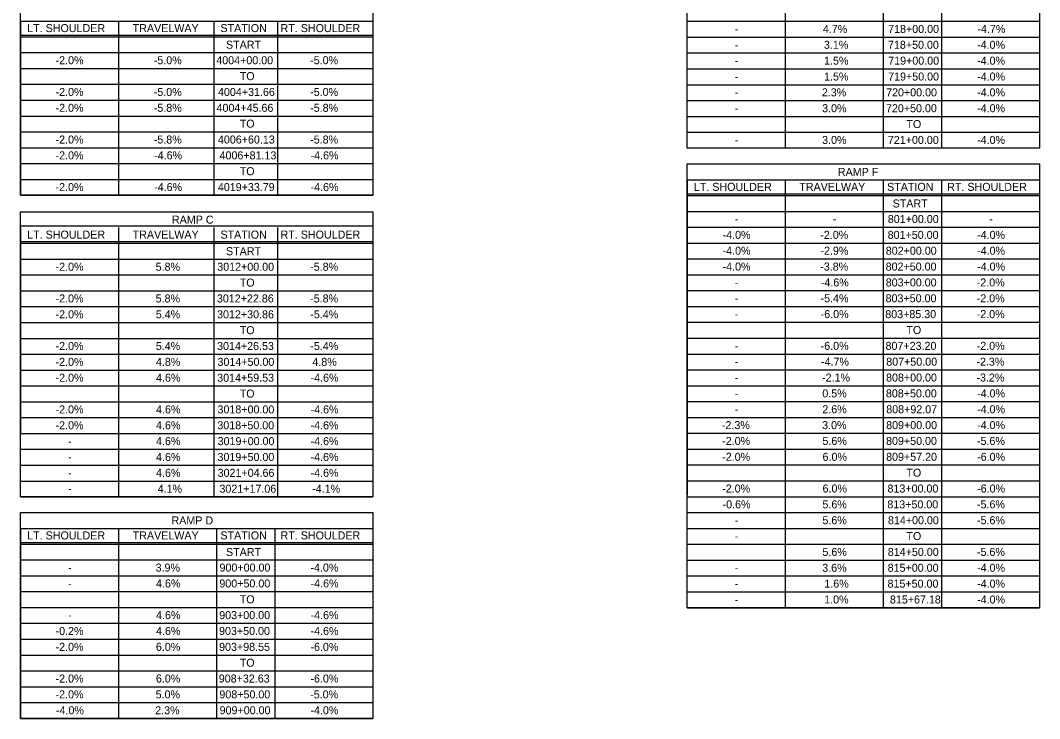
# Model space of a CAD drawing. Extents: x -15318841 to 1762012, y 465773 to 3693661.
# Drawn here: x -15310618.3 to -15310236.2, y 3690925.6 to 3691187.3 of the extents above; entities that cross this region are included whole.
import ezdxf

# ---------------------------------------------------------------- set-up
doc = ezdxf.new("R2010")
doc.units = 0
doc.layers.add('BORDER', color=7, linetype='Continuous')
doc.layers.add('DIMENSIONS', color=7, linetype='Continuous')

msp = doc.modelspace()

# ---------------------------------------------------------------- linework, layer by layer
at = {"layer": 'BORDER'}
for p, q in [((-15310331.64, 3691305.74), (-15310331.64, 3691139.41)), ((-15310294.87, 3691305.74), (-15310294.87, 3691139.41)), ((-15310273, 3691305.74), (-15310273, 3691139.41)), ((-15310618.33, 3691187.04), (-15310618.33, 3691121.74)), ((-15310581.57, 3691187.04), (-15310581.57, 3691121.74)), ((-15310545.8, 3691187.04), (-15310545.8, 3691121.74)), ((-15310521.92, 3691187.04), (-15310521.92, 3691121.74)), ((-15310486.16, 3691187.04), (-15310486.16, 3691121.74)), ((-15310368.41, 3691186.96), (-15310236.23, 3691186.96)), ((-15310618.33, 3691181.76), (-15310486.16, 3691181.76)), ((-15310618.33, 3691181.16), (-15310486.16, 3691181.16)), ((-15310368.41, 3691181.01), (-15310236.23, 3691181.01)), ((-15310618.33, 3691175.22), (-15310486.16, 3691175.22)), ((-15310618.33, 3691175.22), (-15310486.16, 3691175.22)), ((-15310618.33, 3691175.22), (-15310486.16, 3691175.22)), ((-15310368.41, 3691175.07), (-15310236.23, 3691175.07)), ((-15310618.33, 3691169.28), (-15310486.16, 3691169.28)), ((-15310368.41, 3691169.13), (-15310236.23, 3691169.13)), ((-15310618.33, 3691163.33), (-15310486.16, 3691163.33)), ((-15310368.41, 3691163.18), (-15310236.23, 3691163.18)), ((-15310618.33, 3691157.39), (-15310486.16, 3691157.39)), ((-15310368.41, 3691157.24), (-15310236.23, 3691157.24)), ((-15310618.33, 3691151.45), (-15310486.16, 3691151.45)), ((-15310368.41, 3691151.3), (-15310236.23, 3691151.3)), ((-15310618.33, 3691145.51), (-15310486.16, 3691145.51)), ((-15310368.41, 3691145.36), (-15310236.23, 3691145.36)), ((-15310618.33, 3691139.56), (-15310486.16, 3691139.56)), ((-15310618.33, 3691133.62), (-15310486.16, 3691133.62)), ((-15310618.33, 3691127.68), (-15310486.16, 3691127.68)), ((-15310368.41, 3691127.53), (-15310368.41, 3691009.33)), ((-15310331.64, 3691127.53), (-15310331.64, 3690967.14)), ((-15310294.87, 3691127.53), (-15310294.87, 3690967.14)), ((-15310273, 3691127.53), (-15310273, 3690967.14)), ((-15310618.33, 3691121.74), (-15310486.16, 3691121.74)), ((-15310368.41, 3691122.25), (-15310236.23, 3691122.25)), ((-15310368.41, 3691121.65), (-15310236.23, 3691121.65)), ((-15310368.41, 3691115.71), (-15310236.23, 3691115.71)), ((-15310368.41, 3691115.71), (-15310236.23, 3691115.71)), ((-15310368.41, 3691115.71), (-15310236.23, 3691115.71)), ((-15310618.33, 3691109.63), (-15310618.33, 3691032.45)), ((-15310581.57, 3691109.63), (-15310581.57, 3691008.67)), ((-15310545.8, 3691109.63), (-15310545.8, 3691008.67)), ((-15310521.92, 3691109.63), (-15310521.92, 3691008.67)), ((-15310486.16, 3691109.63), (-15310486.16, 3691032.45)), ((-15310368.41, 3691109.77), (-15310236.23, 3691109.77)), ((-15310618.33, 3691104.35), (-15310486.16, 3691104.35)), ((-15310618.33, 3691103.76), (-15310486.16, 3691103.76)), ((-15310368.41, 3691103.82), (-15310236.23, 3691103.82)), ((-15310618.33, 3691097.81), (-15310486.16, 3691097.81)), ((-15310618.33, 3691097.81), (-15310486.16, 3691097.81)), ((-15310618.33, 3691097.81), (-15310486.16, 3691097.81)), ((-15310368.41, 3691097.88), (-15310236.23, 3691097.88)), ((-15310618.33, 3691091.87), (-15310486.16, 3691091.87)), ((-15310368.41, 3691091.94), (-15310236.23, 3691091.94)), ((-15310618.33, 3691085.93), (-15310486.16, 3691085.93)), ((-15310368.41, 3691085.99), (-15310236.23, 3691085.99)), ((-15310618.33, 3691079.99), (-15310486.16, 3691079.99)), ((-15310368.41, 3691080.05), (-15310236.23, 3691080.05)), ((-15310618.33, 3691074.04), (-15310486.16, 3691074.04)), ((-15310368.41, 3691074.11), (-15310236.23, 3691074.11)), ((-15310618.33, 3691068.1), (-15310486.16, 3691068.1)), ((-15310368.41, 3691068.17), (-15310236.23, 3691068.17)), ((-15310618.33, 3691062.16), (-15310486.16, 3691062.16)), ((-15310368.41, 3691062.22), (-15310236.23, 3691062.22)), ((-15310618.33, 3691056.22), (-15310486.16, 3691056.22)), ((-15310368.41, 3691056.28), (-15310236.23, 3691056.28)), ((-15310618.33, 3691050.27), (-15310486.16, 3691050.27)), ((-15310368.41, 3691050.34), (-15310236.23, 3691050.34)), ((-15310618.33, 3691044.33), (-15310486.16, 3691044.33)), ((-15310368.41, 3691044.4), (-15310236.23, 3691044.4)), ((-15310618.33, 3691038.39), (-15310486.16, 3691038.39)), ((-15310368.41, 3691038.45), (-15310236.23, 3691038.45)), ((-15310618.33, 3691032.45), (-15310486.16, 3691032.45)), ((-15310368.41, 3691032.51), (-15310236.23, 3691032.51)), ((-15310618.33, 3691026.5), (-15310486.16, 3691026.5)), ((-15310368.41, 3691026.57), (-15310236.23, 3691026.57)), ((-15310618.33, 3691020.56), (-15310486.16, 3691020.56)), ((-15310368.41, 3691020.63), (-15310236.23, 3691020.63)), ((-15310618.33, 3691014.62), (-15310486.16, 3691014.62)), ((-15310368.41, 3691014.68), (-15310236.23, 3691014.68)), ((-15310618.33, 3691008.67), (-15310486.16, 3691008.67)), ((-15310368.41, 3691008.74), (-15310236.23, 3691008.74)), ((-15310368.41, 3691002.8), (-15310236.23, 3691002.8)), ((-15310618.33, 3690996.87), (-15310618.33, 3690925.56)), ((-15310581.57, 3690996.87), (-15310581.57, 3690925.56)), ((-15310544.8, 3690996.87), (-15310544.8, 3690925.56)), ((-15310522.92, 3690996.87), (-15310522.92, 3690925.56)), ((-15310368.41, 3690996.85), (-15310236.23, 3690996.85)), ((-15310618.33, 3690991.59), (-15310486.16, 3690991.59)), ((-15310618.33, 3690990.99), (-15310486.16, 3690990.99)), ((-15310368.41, 3690990.91), (-15310236.23, 3690990.91)), ((-15310618.33, 3690985.05), (-15310486.16, 3690985.05)), ((-15310618.33, 3690985.05), (-15310486.16, 3690985.05)), ((-15310618.33, 3690985.05), (-15310486.16, 3690985.05)), ((-15310368.41, 3690984.97), (-15310236.23, 3690984.97)), ((-15310618.33, 3690979.11), (-15310486.16, 3690979.11)), ((-15310368.41, 3690979.03), (-15310236.23, 3690979.03)), ((-15310618.33, 3690973.16), (-15310486.16, 3690973.16)), ((-15310368.41, 3690973.08), (-15310236.23, 3690973.08)), ((-15310618.33, 3690967.22), (-15310486.16, 3690967.22)), ((-15310368.41, 3690967.14), (-15310236.23, 3690967.14)), ((-15310618.33, 3690961.28), (-15310486.16, 3690961.28)), ((-15310618.33, 3690955.34), (-15310486.16, 3690955.34)), ((-15310618.33, 3690949.39), (-15310486.16, 3690949.39)), ((-15310618.33, 3690943.45), (-15310486.16, 3690943.45)), ((-15310618.33, 3690937.51), (-15310486.16, 3690937.51)), ((-15310618.33, 3690931.57), (-15310486.16, 3690931.57)), ((-15310618.33, 3690925.62), (-15310486.16, 3690925.62))]:
    msp.add_line(p, q, dxfattribs=at)
for points in [[(-15310368.41, 3691305.74), (-15310236.23, 3691305.74), (-15310236.23, 3691139.41), (-15310368.41, 3691139.41)], [(-15310618.33, 3691187.04), (-15310486.16, 3691187.04), (-15310486.16, 3691121.74), (-15310618.33, 3691121.74)], [(-15310368.41, 3691127.53), (-15310236.23, 3691127.53), (-15310236.23, 3690967.14), (-15310368.41, 3690967.14)], [(-15310618.33, 3691110.23), (-15310486.16, 3691110.23), (-15310486.16, 3691008.67), (-15310618.33, 3691008.67)], [(-15310618.33, 3690996.87), (-15310486.16, 3690996.87), (-15310486.16, 3690925.56), (-15310618.33, 3690925.56)]]:
    msp.add_lwpolyline(points, close=True, dxfattribs=at)
for points in [[(-15310618.33, 3691187.04), (-15310618.33, 3691192.98), (-15310486.16, 3691192.98), (-15310486.16, 3691187.04)], [(-15310368.41, 3691127.53), (-15310368.41, 3691133.47), (-15310236.23, 3691133.47), (-15310236.23, 3691127.53)], [(-15310618.33, 3691109.63), (-15310618.33, 3691115.58), (-15310486.16, 3691115.58), (-15310486.16, 3691109.63)], [(-15310618.33, 3690996.87), (-15310618.33, 3691002.81), (-15310486.16, 3691002.81), (-15310486.16, 3690996.87)]]:
    msp.add_lwpolyline(points, dxfattribs=at)

# ---------------------------------------------------------------- texts
at = {"layer": 'DIMENSIONS'}
for s, p in [('LT. SHOULDER', (-15310615.78, 3691182.9)), ('TRAVELWAY', (-15310576.24, 3691182.9)), ('STATION', (-15310543.33, 3691182.9)), ('RT. SHOULDER', (-15310520.8, 3691182.9)), ('4.7%', (-15310317.48, 3691182.58)), ('718+00.00', (-15310293.02, 3691182.58)), ('-4.7%', (-15310259.55, 3691182.58)), ('-', (-15310350.53, 3691182.58)), ('START', (-15310541.26, 3691176.68)), ('-', (-15310350.53, 3691176.64)), ('3.1%', (-15310317.1, 3691176.64)), ('718+50.00', (-15310293.07, 3691176.64)), ('-4.0%', (-15310259.66, 3691176.64)), ('-2.0%', (-15310605.14, 3691170.85)), ('-5.0%', (-15310568.33, 3691170.85)), ('4004+00.00', (-15310544.89, 3691170.85)), ('-5.0%', (-15310509.69, 3691170.85)), ('1.5%', (-15310317.03, 3691170.7)), ('719+00.00', (-15310292.98, 3691170.7)), ('-4.0%', (-15310259.66, 3691170.7)), ('-', (-15310350.53, 3691170.7)), ('TO', (-15310536.1, 3691164.9)), ('-', (-15310350.53, 3691164.75)), ('1.5%', (-15310317.03, 3691164.75)), ('719+50.00', (-15310293.02, 3691164.75)), ('-4.0%', (-15310259.66, 3691164.75)), ('-2.0%', (-15310605.14, 3691158.96)), ('-5.0%', (-15310568.33, 3691158.96)), ('4004+31.66', (-15310544.25, 3691158.96)), ('-5.0%', (-15310509.69, 3691158.96)), ('-', (-15310350.53, 3691158.81)), ('2.3%', (-15310317.86, 3691158.81)), ('720+00.00', (-15310293.78, 3691158.81)), ('-4.0%', (-15310259.66, 3691158.81)), ('-2.0%', (-15310605.14, 3691153.02)), ('-5.8%', (-15310568.33, 3691153.02)), ('4004+45.66', (-15310544.79, 3691153.02)), ('-5.8%', (-15310509.69, 3691153.02)), ('3.0%', (-15310317.76, 3691152.87)), ('720+50.00', (-15310293.83, 3691152.87)), ('-4.0%', (-15310259.66, 3691152.87)), ('-', (-15310350.53, 3691152.87)), ('TO', (-15310536.1, 3691147.08)), ('TO', (-15310286.17, 3691146.93)), ('-2.0%', (-15310605.14, 3691141.13)), ('-5.8%', (-15310568.33, 3691141.13)), ('4006+60.13', (-15310544.28, 3691141.13)), ('-5.8%', (-15310509.69, 3691141.13)), ('3.0%', (-15310317.76, 3691140.98)), ('721+00.00', (-15310293.12, 3691140.98)), ('-4.0%', (-15310259.66, 3691140.98)), ('-', (-15310350.53, 3691140.98)), ('-2.0%', (-15310605.14, 3691135.19)), ('-4.6%', (-15310568.19, 3691135.19)), ('4006+81.13', (-15310543.67, 3691135.19)), ('-4.6%', (-15310509.54, 3691135.19)), ('TO', (-15310536.1, 3691129.25)), ('RAMP F', (-15310311.86, 3691129)), ('-2.0%', (-15310605.14, 3691123.31)), ('-4.6%', (-15310568.19, 3691123.31)), ('4019+33.79', (-15310544.3, 3691123.31)), ('-4.6%', (-15310509.54, 3691123.31)), ('LT. SHOULDER', (-15310365.85, 3691123.39)), ('TRAVELWAY', (-15310326.32, 3691123.39)), ('STATION', (-15310293.41, 3691123.39)), ('RT. SHOULDER', (-15310270.87, 3691123.39)), ('START', (-15310291.33, 3691117.16)), ('RAMP C', (-15310561.52, 3691111.11)), ('-', (-15310350.53, 3691111.33)), ('-', (-15310313.76, 3691111.33)), ('801+00.00', (-15310293.14, 3691111.33)), ('-', (-15310255.12, 3691111.33)), ('LT. SHOULDER', (-15310615.78, 3691105.49)), ('TRAVELWAY', (-15310576.24, 3691105.49)), ('STATION', (-15310543.33, 3691105.49)), ('RT. SHOULDER', (-15310520.8, 3691105.49)), ('-4.0%', (-15310355.08, 3691105.39)), ('-2.0%', (-15310318.45, 3691105.39)), ('801+50.00', (-15310293.19, 3691105.39)), ('-4.0%', (-15310259.66, 3691105.39)), ('START', (-15310541.26, 3691099.27)), ('-4.0%', (-15310355.08, 3691099.45)), ('-2.9%', (-15310318.4, 3691099.45)), ('802+00.00', (-15310293.9, 3691099.45)), ('-4.0%', (-15310259.66, 3691099.45)), ('-2.0%', (-15310605.14, 3691093.44)), ('5.8%', (-15310567.62, 3691093.44)), ('3012+00.00', (-15310544.53, 3691093.44)), ('-5.8%', (-15310509.69, 3691093.44)), ('-4.0%', (-15310355.08, 3691093.51)), ('-3.8%', (-15310318.47, 3691093.51)), ('802+50.00', (-15310293.95, 3691093.51)), ('-4.0%', (-15310259.66, 3691093.51)), ('TO', (-15310536.1, 3691087.5)), ('-4.6%', (-15310318.26, 3691087.56)), ('803+00.00', (-15310293.92, 3691087.56)), ('-2.0%', (-15310259.81, 3691087.56)), ('-', (-15310350.53, 3691087.56)), ('-2.0%', (-15310605.14, 3691081.56)), ('5.8%', (-15310567.62, 3691081.56)), ('3012+22.86', (-15310544.67, 3691081.56)), ('-5.8%', (-15310509.69, 3691081.56)), ('-', (-15310350.53, 3691081.62)), ('-5.4%', (-15310318.35, 3691081.62)), ('803+50.00', (-15310293.97, 3691081.62)), ('-2.0%', (-15310259.81, 3691081.62)), ('-2.0%', (-15310605.14, 3691075.61)), ('5.4%', (-15310567.57, 3691075.61)), ('3012+30.86', (-15310544.6, 3691075.61)), ('-5.4%', (-15310509.64, 3691075.61)), ('-6.0%', (-15310318.31, 3691075.68)), ('803+85.30', (-15310294.09, 3691075.68)), ('-2.0%', (-15310259.81, 3691075.68)), ('-', (-15310350.53, 3691075.68)), ('TO', (-15310536.1, 3691069.67)), ('TO', (-15310286.17, 3691069.74)), ('-2.0%', (-15310605.14, 3691063.73)), ('5.4%', (-15310567.57, 3691063.73)), ('3014+26.53', (-15310544.59, 3691063.73)), ('-5.4%', (-15310509.64, 3691063.73)), ('-6.0%', (-15310318.31, 3691063.79)), ('807+23.20', (-15310293.99, 3691063.79)), ('-2.0%', (-15310259.81, 3691063.79)), ('-', (-15310350.53, 3691063.79)), ('-2.0%', (-15310605.14, 3691057.79)), ('4.8%', (-15310567.53, 3691057.79)), ('3014+50.00', (-15310544.44, 3691057.79)), ('4.8%', (-15310508.88, 3691057.79)), ('-', (-15310350.53, 3691057.85)), ('-4.7%', (-15310318.19, 3691057.85)), ('807+50.00', (-15310293.73, 3691057.85)), ('-2.3%', (-15310259.92, 3691057.85)), ('-2.0%', (-15310605.14, 3691051.84)), ('4.6%', (-15310567.48, 3691051.84)), ('3014+59.53', (-15310544.54, 3691051.84)), ('-4.6%', (-15310509.54, 3691051.84)), ('-', (-15310350.53, 3691051.91)), ('-2.1%', (-15310317.79, 3691051.91)), ('808+00.00', (-15310293.8, 3691051.91)), ('-3.2%', (-15310259.92, 3691051.91)), ('TO', (-15310536.1, 3691045.9)), ('0.5%', (-15310317.69, 3691045.97)), ('808+50.00', (-15310293.85, 3691045.97)), ('-4.0%', (-15310259.66, 3691045.97)), ('-', (-15310350.53, 3691045.97)), ('-2.0%', (-15310605.14, 3691039.96)), ('4.6%', (-15310567.48, 3691039.96)), ('3018+00.00', (-15310544.44, 3691039.96)), ('-4.6%', (-15310509.54, 3691039.96)), ('-', (-15310350.53, 3691040.02)), ('2.6%', (-15310317.69, 3691040.02)), ('808+92.07', (-15310293.73, 3691040.02)), ('-4.0%', (-15310259.66, 3691040.02)), ('-2.0%', (-15310605.14, 3691034.01)), ('4.6%', (-15310567.48, 3691034.01)), ('3018+50.00', (-15310544.49, 3691034.01)), ('-4.6%', (-15310509.54, 3691034.01)), ('-2.3%', (-15310355.34, 3691034.08)), ('3.0%', (-15310317.76, 3691034.08)), ('809+00.00', (-15310293.76, 3691034.08)), ('-4.0%', (-15310259.66, 3691034.08)), ('-', (-15310600.46, 3691028.07)), ('4.6%', (-15310567.48, 3691028.07)), ('3019+00.00', (-15310544.39, 3691028.07)), ('-4.6%', (-15310509.54, 3691028.07)), ('-2.0%', (-15310355.22, 3691028.14)), ('5.6%', (-15310317.65, 3691028.14)), ('809+50.00', (-15310293.8, 3691028.14)), ('-5.6%', (-15310259.71, 3691028.14)), ('4.6%', (-15310567.48, 3691022.13)), ('3019+50.00', (-15310544.44, 3691022.13)), ('-4.6%', (-15310509.54, 3691022.13)), ('-2.0%', (-15310355.22, 3691022.19)), ('6.0%', (-15310317.6, 3691022.19)), ('809+57.20', (-15310293.78, 3691022.19)), ('-6.0%', (-15310259.66, 3691022.19)), ('-', (-15310600.46, 3691022.13)), ('-', (-15310600.46, 3691016.19)), ('4.6%', (-15310567.48, 3691016.19)), ('3021+04.66', (-15310544.39, 3691016.19)), ('-4.6%', (-15310509.54, 3691016.19)), ('TO', (-15310286.17, 3691016.25)), ('4.1%', (-15310566.87, 3691010.24)), ('3021+17.06', (-15310543.71, 3691010.24)), ('-4.1%', (-15310508.93, 3691010.24)), ('-2.0%', (-15310355.22, 3691010.31)), ('6.0%', (-15310317.6, 3691010.31)), ('813+00.00', (-15310293.26, 3691010.31)), ('-6.0%', (-15310259.66, 3691010.31)), ('-', (-15310600.46, 3691010.24)), ('-0.6%', (-15310355.08, 3691004.37)), ('5.6%', (-15310317.65, 3691004.37)), ('813+50.00', (-15310293.31, 3691004.37)), ('-5.6%', (-15310259.71, 3691004.37)), ('RAMP D', (-15310561.68, 3690998.34)), ('-', (-15310350.53, 3690998.42)), ('5.6%', (-15310317.65, 3690998.42)), ('814+00.00', (-15310293.09, 3690998.42)), ('-5.6%', (-15310259.71, 3690998.42)), ('LT. SHOULDER', (-15310615.78, 3690992.73)), ('TRAVELWAY', (-15310576.24, 3690992.73)), ('STATION', (-15310543.33, 3690992.73)), ('RT. SHOULDER', (-15310520.8, 3690992.73)), ('TO', (-15310286.17, 3690992.48)), ('-', (-15310350.53, 3690992.48)), ('START', (-15310541.26, 3690986.51)), ('5.6%', (-15310317.65, 3690986.54)), ('814+50.00', (-15310293.14, 3690986.54)), ('-5.6%', (-15310259.71, 3690986.54)), ('3.9%', (-15310567.64, 3690980.68)), ('900+00.00', (-15310543.68, 3690980.68)), ('-4.0%', (-15310509.59, 3690980.68)), ('3.6%', (-15310317.72, 3690980.6)), ('815+00.00', (-15310293.19, 3690980.6)), ('-4.0%', (-15310259.66, 3690980.6)), ('-', (-15310600.46, 3690980.68)), ('-', (-15310350.53, 3690980.6)), ('-', (-15310600.46, 3690974.73)), ('4.6%', (-15310567.48, 3690974.73)), ('900+50.00', (-15310543.73, 3690974.73)), ('-4.6%', (-15310509.54, 3690974.73)), ('-', (-15310350.53, 3690974.65)), ('1.6%', (-15310316.94, 3690974.65)), ('815+50.00', (-15310293.24, 3690974.65)), ('-4.0%', (-15310259.66, 3690974.65)), ('TO', (-15310536.1, 3690968.79)), ('1.0%', (-15310316.99, 3690968.71)), ('815+67.18', (-15310292.35, 3690968.71)), ('-4.0%', (-15310259.66, 3690968.71)), ('-', (-15310350.53, 3690968.71)), ('-', (-15310600.46, 3690962.85)), ('4.6%', (-15310567.48, 3690962.85)), ('903+00.00', (-15310543.8, 3690962.85)), ('-4.6%', (-15310509.54, 3690962.85)), ('-0.2%', (-15310605.14, 3690956.91)), ('4.6%', (-15310567.48, 3690956.91)), ('903+50.00', (-15310543.85, 3690956.91)), ('-4.6%', (-15310509.54, 3690956.91)), ('-2.0%', (-15310605.14, 3690950.96)), ('6.0%', (-15310567.53, 3690950.96)), ('903+98.55', (-15310543.84, 3690950.96)), ('-6.0%', (-15310509.59, 3690950.96)), ('TO', (-15310536.1, 3690945.02)), ('-2.0%', (-15310605.14, 3690939.08)), ('6.0%', (-15310567.53, 3690939.08)), ('908+32.63', (-15310543.95, 3690939.08)), ('-6.0%', (-15310509.59, 3690939.08)), ('-2.0%', (-15310605.14, 3690933.14)), ('5.0%', (-15310567.62, 3690933.14)), ('908+50.00', (-15310543.73, 3690933.14)), ('-5.0%', (-15310509.69, 3690933.14)), ('-4.0%', (-15310605, 3690927.19)), ('2.3%', (-15310567.79, 3690927.19)), ('909+00.00', (-15310543.64, 3690927.19)), ('-4.0%', (-15310509.59, 3690927.19))]:
    msp.add_text(s, height=3, dxfattribs=at).set_placement(p)

doc.saveas('drawing.dxf')
